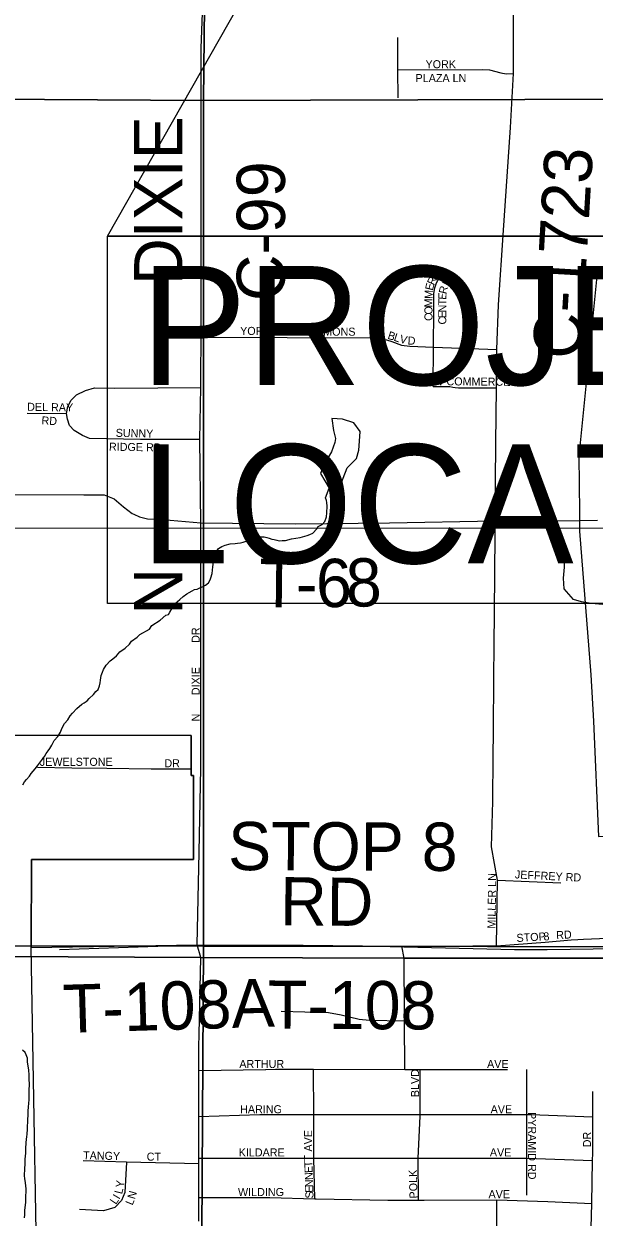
# Model space of a CAD drawing. Extents: x 8.5 to 81.5, y -1.2 to 22.4.
# Drawn here: x 51.992 to 52.663, y 15.445 to 16.85 of the extents above; entities that cross this region are included whole.
import ezdxf

# ---------------------------------------------------------------- set-up
doc = ezdxf.new("R2010")
doc.units = 0
for name, color, linetype in [('GM_X_City_Street', 7, 'Continuous'), ('GM_X_City_Street_Text', 7, 'Continuous'), ('GM_X_Corporation', 7, 'Continuous'), ('GM_X_County_Road', 7, 'Continuous'), ('GM_X_County_Road_Text', 7, 'Continuous'), ('GM_X_Interchange_Ramps', 7, 'Continuous'), ('GM_X_Minor_Lake', 7, 'Continuous'), ('GM_X_Minor_River', 7, 'Continuous'), ('GM_X_Section', 7, 'Continuous'), ('GM_X_Township', 7, 'Continuous'), ('GM_X_Township_Road', 7, 'Continuous'), ('GM_X_Township_Road_Text', 7, 'Continuous'), ('GM_X_Township_Subdivision', 7, 'Continuous'), ('GM_X_Township_Subdivision_Text', 7, 'Continuous'), ('SH_Text', 7, 'Continuous')]:
    doc.layers.add(name, color=color, linetype=linetype)

msp = doc.modelspace()

# ---------------------------------------------------------------- linework, layer by layer
at = {"layer": 'GM_X_City_Street'}
for points in [[(52.5465, 16.2011), (52.5469, 16.2508)], [(52.5454, 16.0819), (52.5457, 16.117), (52.5465, 16.2011)], [(52.1991, 15.9147), (52.2003, 15.9732), (52.2003, 16.0131), (52.2003, 16.1532)], [(52.5483, 15.7647), (52.5495, 15.8419), (52.5425, 15.881), (52.5441, 15.9345), (52.5444, 15.9879), (52.5447, 16.0167), (52.5454, 16.0819)], [(52.008, 15.9748), (52.0484, 15.9743), (52.0897, 15.9738), (52.1417, 15.9728), (52.1886, 15.9728)], [(52.1982, 15.8749), (52.1991, 15.9147)], [(52.1983, 15.66), (52.2003, 15.7506), (52.196, 15.7656), (52.1982, 15.8749)], [(52.5495, 15.8419), (52.6242, 15.8389)], [(52.5204, 15.7644), (52.5483, 15.7647), (52.6057, 15.7689), (52.6364, 15.7716), (52.6441, 15.772)], [(52.6441, 15.772), (52.651, 15.7724), (52.679, 15.7735)]]:
    msp.add_lwpolyline(points, dxfattribs=at)
at = {"layer": 'GM_X_Corporation'}
for points in [[(52.6937, 16.256), (51.6568, 16.2563), (51.671, 16.2128), (51.6596, 16.2043), (51.6444, 16.1826), (51.6447, 16.1693), (51.6783, 16.1687), (51.6973, 16.1563), (51.7134, 16.1365), (51.7024, 16.0787), (51.7477, 16.0787), (51.7477, 16.0125), (52.1887, 16.0124), (52.1887, 15.965), (52.1915, 15.965), (52.1915, 15.8662), (52.0008, 15.8662), (52.0006, 15.7624), (52.196, 15.7656), (52.3208, 15.7651), (52.3907, 15.7645), (52.5695, 15.7602), (52.6081, 15.7601), (52.771, 15.7625)], [(52.0096, 15.25), (52.0006, 15.7624), (52.0008, 15.8662), (52.1915, 15.8662), (52.1915, 15.965), (52.1887, 15.965), (52.1887, 16.0124), (51.7477, 16.0125), (51.6967, 16.0125), (51.6913, 15.9108), (51.6902, 15.7628), (51.6397, 15.762), (51.5788, 15.7609), (51.5389, 15.7615), (51.5388, 15.4213)]]:
    msp.add_lwpolyline(points, dxfattribs=at)
at = {"layer": 'GM_X_County_Road'}
for points in [[(52.2003, 16.1532), (52.2003, 16.2526), (52.2003, 16.2626), (52.199, 16.3609), (52.2003, 16.4222), (52.2004, 16.4349), (52.2008, 16.4813), (52.2007, 16.8218), (52.204, 16.9161), (52.204, 16.9504), (52.204, 17.0069), (52.2074, 17.1214), (52.2073, 17.217), (52.2073, 17.3093), (52.2079, 17.4425), (52.2107, 17.5455), (52.2107, 17.712), (52.2092, 17.8004)], [(52.5469, 16.2508), (52.547, 16.2649), (52.5478, 16.3566), (52.5484, 16.4219), (52.5487, 16.4669), (52.5508, 16.5193), (52.5568, 16.6074), (52.5596, 16.6533), (52.5649, 16.7285), (52.5685, 16.7919), (52.5684, 16.8692), (52.572, 16.9648), (52.5716, 17.035), (52.5715, 17.0497), (52.572, 17.1033), (52.572, 17.1627), (52.5744, 17.2103), (52.5768, 17.2364), (52.5815, 17.2555), (52.5934, 17.2745), (52.6101, 17.2935)], [(52.198, 15.4403), (52.198, 15.468), (52.198, 15.5079), (52.198, 15.5143), (52.198, 15.5342), (52.198, 15.5444), (52.198, 15.5636), (52.198, 15.6175), (52.198, 15.6459), (52.1983, 15.66)]]:
    msp.add_lwpolyline(points, dxfattribs=at)
at = {"layer": 'GM_X_Interchange_Ramps'}
for points in [[(52.6792, 16.557), (52.6671, 16.557), (52.6508, 16.3963), (52.6455, 16.3414), (52.6462, 16.2753), (52.6462, 16.2654)], [(52.6462, 16.2654), (52.6462, 16.2529), (52.6595, 16.0836), (52.6625, 16.029), (52.6687, 15.8932), (52.6792, 15.8938)]]:
    msp.add_lwpolyline(points, dxfattribs=at)
at = {"layer": 'GM_X_Minor_Lake'}
for points in [[(52.3513, 16.3037), (52.363, 16.3031), (52.3678, 16.3155), (52.3726, 16.3276), (52.3835, 16.3384), (52.3863, 16.3482), (52.3869, 16.3589), (52.3879, 16.3702), (52.3805, 16.3803), (52.3669, 16.3847), (52.3544, 16.3857), (52.3564, 16.3716), (52.3589, 16.3621)], [(52.3589, 16.3621), (52.358, 16.3575), (52.354, 16.3462), (52.3462, 16.3335), (52.341, 16.321), (52.3513, 16.3037)]]:
    msp.add_lwpolyline(points, dxfattribs=at)
at = {"layer": 'GM_X_Minor_River'}
for points in [[(52.0809, 16.0707), (52.0817, 16.0741), (52.0822, 16.0775), (52.083, 16.0828), (52.0843, 16.087), (52.0858, 16.09), (52.0886, 16.0949), (52.0936, 16.1001), (52.0967, 16.1027), (52.101, 16.106), (52.1049, 16.1109), (52.111, 16.1149), (52.1161, 16.1198), (52.1184, 16.1232), (52.1253, 16.128), (52.1284, 16.1313), (52.1396, 16.1375), (52.1427, 16.1417), (52.1523, 16.1479), (52.1589, 16.1539), (52.1623, 16.1546), (52.1639, 16.1576), (52.1666, 16.1621), (52.1698, 16.1674), (52.1729, 16.17), (52.1756, 16.1726), (52.1794, 16.1759), (52.1837, 16.1789), (52.1864, 16.1807), (52.1902, 16.1825), (52.1929, 16.184), (52.1959, 16.1847), (52.1998, 16.1865), (52.2028, 16.1876), (52.2059, 16.1894), (52.2094, 16.192), (52.2113, 16.1954), (52.2121, 16.198), (52.2134, 16.203), (52.2138, 16.2068), (52.2143, 16.2109), (52.2147, 16.2136), (52.2148, 16.2166), (52.2152, 16.2197), (52.2157, 16.2223), (52.2165, 16.2257), (52.2181, 16.2287), (52.2212, 16.2325), (52.225, 16.235), (52.2289, 16.2365), (52.2346, 16.2379), (52.2407, 16.2385), (52.2433, 16.2389), (52.2471, 16.2392), (52.2502, 16.2399), (52.2536, 16.2413), (52.2594, 16.2435), (52.2655, 16.246), (52.2685, 16.2463), (52.272, 16.2463), (52.275, 16.2462), (52.278, 16.2454), (52.2806, 16.2446), (52.284, 16.2433), (52.2867, 16.2429), (52.2897, 16.2421), (52.2923, 16.2417), (52.2961, 16.242), (52.2999, 16.2419), (52.3072, 16.244), (52.3171, 16.2453), (52.3255, 16.2478), (52.3285, 16.2489), (52.332, 16.2504), (52.337, 16.2556), (52.3386, 16.2582), (52.3432, 16.2608), (52.3463, 16.2641), (52.3483, 16.2698), (52.3488, 16.2743), (52.349, 16.2823), (52.3487, 16.2865), (52.3483, 16.2892), (52.3471, 16.2923), (52.3513, 16.3037)], [(52.6737, 16.1667), (52.6597, 16.1677), (52.6487, 16.1695), (52.6389, 16.1724), (52.6281, 16.1851), (52.6272, 16.1977), (52.6283, 16.2106), (52.6289, 16.2223), (52.623, 16.235), (52.6214, 16.248)], [(51.9908, 15.9543), (51.9924, 15.9577), (51.9948, 15.9603), (51.9983, 15.9644), (52.0006, 15.9674), (52.0053, 15.973), (52.008, 15.9767), (52.0138, 15.9842), (52.0162, 15.9876), (52.0182, 15.991), (52.0205, 15.994), (52.0225, 15.997), (52.0248, 16.0007), (52.0276, 16.0064), (52.0319, 16.0112), (52.035, 16.0161), (52.0366, 16.0206), (52.0398, 16.0263), (52.0436, 16.0308), (52.0464, 16.0353), (52.0491, 16.0386), (52.0542, 16.0439), (52.0603, 16.0491), (52.063, 16.0509), (52.0665, 16.0531), (52.0688, 16.0557), (52.0739, 16.0606), (52.0766, 16.0639), (52.0793, 16.0665), (52.0809, 16.0707)], [(51.9925, 15.4443), (51.9929, 15.4477), (51.993, 15.453), (51.994, 15.4621), (51.9941, 15.4697), (51.9946, 15.4751), (51.9947, 15.4785), (51.9937, 15.4853), (51.9931, 15.4903), (51.9927, 15.4937), (51.9929, 15.5021), (51.9934, 15.5074), (51.9935, 15.5131), (51.9941, 15.5203), (51.9942, 15.526), (51.9947, 15.5325), (51.9951, 15.5367), (51.9952, 15.5397), (51.9957, 15.5427), (51.9961, 15.5484), (51.9964, 15.5602), (51.9969, 15.5648), (51.997, 15.5701), (51.9974, 15.5746), (51.9975, 15.5792), (51.998, 15.583), (51.9982, 15.594), (51.9984, 15.6016), (51.9981, 15.6073), (51.9982, 15.61), (51.9979, 15.6127), (51.9976, 15.618), (51.9973, 15.621), (51.9966, 15.6252), (51.9963, 15.6279), (51.996, 15.6321), (51.9945, 15.6363), (51.9935, 15.639), (51.9901, 15.6417)]]:
    msp.add_lwpolyline(points, dxfattribs=at)
at = {"layer": 'GM_X_Section'}
for points in [[(51.2117, 17.8427), (52.2149, 17.8371), (52.2034, 16.7602), (51.2044, 16.7664)], [(52.2149, 17.8371), (53.2272, 17.8352), (53.2124, 16.7633), (52.2034, 16.7602)], [(51.2044, 16.7664), (52.2034, 16.7602), (52.2033, 15.7642), (51.1955, 15.7645)], [(52.2034, 16.7602), (53.2124, 16.7633), (53.2065, 15.7628), (52.2033, 15.7642)], [(51.1955, 15.7645), (52.2033, 15.7642), (52.1975, 14.7482), (51.1961, 14.7442)], [(52.2033, 15.7642), (53.2065, 15.7628), (53.1998, 14.754), (52.1975, 14.7482)]]:
    msp.add_lwpolyline(points, close=True, dxfattribs=at)
at = {"layer": 'GM_X_Township'}
for points in [[(51.1938, 15.7549), (51.5756, 15.7537), (51.6527, 15.7534), (52.2003, 15.7506), (52.4397, 15.7501), (52.6795, 15.7498)], [(52.6795, 15.7498), (52.4397, 15.7501), (52.2003, 15.7506), (51.6527, 15.7534), (51.5756, 15.7537), (51.1938, 15.7549)]]:
    msp.add_lwpolyline(points, dxfattribs=at)
at = {"layer": 'GM_X_Township_Road'}
for points in [[(51.7005, 16.4905), (51.7271, 16.4919), (51.7446, 16.4912), (51.7616, 16.4898), (51.7748, 16.4823), (51.7808, 16.4766), (51.7883, 16.4599), (51.7883, 16.4386), (51.789, 16.3814), (51.787, 16.3296), (51.7896, 16.3206), (51.7933, 16.3133), (51.7988, 16.307), (51.8047, 16.3023), (51.8134, 16.2983), (51.8287, 16.2959), (51.8909, 16.2965), (52.0626, 16.2957), (52.0863, 16.2957), (52.0982, 16.2909), (52.109, 16.2814), (52.1193, 16.2736), (52.1212, 16.2728)], [(52.1212, 16.2728), (52.1281, 16.2698), (52.1376, 16.2676), (52.1552, 16.2668), (52.2003, 16.2626)], [(52.2003, 16.2626), (52.3119, 16.2617), (52.4226, 16.2628), (52.547, 16.2649), (52.555, 16.265)], [(52.555, 16.265), (52.6462, 16.2654), (52.6674, 16.2657)], [(52.0337, 15.76), (52.196, 15.7656)], [(52.196, 15.7656), (52.3208, 15.7651), (52.3907, 15.7645), (52.4368, 15.7642), (52.5006, 15.7642), (52.5204, 15.7644)]]:
    msp.add_lwpolyline(points, dxfattribs=at)
at = {"layer": 'GM_X_Township_Subdivision'}
for points in [[(52.4324, 16.7964), (52.4324, 16.8307), (52.4323, 16.8344)], [(52.4324, 16.7964), (52.5322, 16.7967), (52.5322, 16.7967), (52.5403, 16.7963), (52.5534, 16.7928), (52.5596, 16.7917), (52.5685, 16.7919)], [(52.4325, 16.7632), (52.4324, 16.7964)], [(52.4737, 16.4232), (52.4742, 16.4696), (52.4746, 16.5128), (52.4748, 16.533), (52.4759, 16.5396), (52.4779, 16.5455), (52.4812, 16.5515)], [(52.2008, 16.4813), (52.4031, 16.4806), (52.4096, 16.4802), (52.4187, 16.4782), (52.4252, 16.4761), (52.4367, 16.4721), (52.4463, 16.4706), (52.4742, 16.4696), (52.5487, 16.4669)], [(52.199, 16.3609), (52.1292, 16.361), (52.0693, 16.362), (52.061, 16.3654), (52.0512, 16.3716), (52.0455, 16.3774), (52.0431, 16.3849), (52.0419, 16.3916), (52.0438, 16.3998), (52.0476, 16.4073), (52.054, 16.4133), (52.0646, 16.4186), (52.0752, 16.4219), (52.0989, 16.4213), (52.2003, 16.4222)], [(52.4737, 16.4232), (52.4934, 16.4232), (52.4971, 16.4226), (52.4999, 16.4222), (52.5038, 16.4219), (52.5484, 16.4219)], [(51.9957, 16.392), (52.0419, 16.3916)], [(52.4405, 15.619), (52.4401, 15.6759), (52.44, 15.683), (52.4397, 15.7501), (52.4368, 15.7642)], [(52.4401, 15.6759), (52.3987, 15.6764), (52.3867, 15.6777), (52.3654, 15.683), (52.3507, 15.6857), (52.2948, 15.6871)], [(52.198, 15.6175), (52.2763, 15.6189), (52.2766, 15.6189)], [(52.2766, 15.6189), (52.2881, 15.6191), (52.3329, 15.6191), (52.4405, 15.619), (52.4587, 15.619), (52.4729, 15.619), (52.4729, 15.619)], [(52.3344, 15.4666), (52.3334, 15.5145), (52.3334, 15.5658), (52.3329, 15.6191)], [(52.4585, 15.5639), (52.4586, 15.5657), (52.4587, 15.5671), (52.4587, 15.619)], [(52.4729, 15.619), (52.522, 15.619), (52.522, 15.619)], [(52.522, 15.619), (52.5613, 15.619)], [(52.584, 15.471), (52.584, 15.5144), (52.584, 15.5657), (52.584, 15.619)], [(52.6599, 15.2337), (52.6584, 15.2939), (52.6584, 15.2969), (52.6596, 15.3441), (52.66, 15.3598), (52.66, 15.4059), (52.66, 15.4325), (52.6606, 15.461), (52.6615, 15.5118), (52.6617, 15.5202), (52.6617, 15.5631), (52.6617, 15.593)], [(52.198, 15.5636), (52.2698, 15.5658), (52.3334, 15.5658), (52.4586, 15.5657), (52.584, 15.5657), (52.5889, 15.5657), (52.6617, 15.5631)], [(52.4564, 15.4648), (52.456, 15.5145), (52.4585, 15.5637), (52.4585, 15.5639)], [(52.1126, 15.5099), (52.1108, 15.4738), (52.1068, 15.4645), (52.0989, 15.4565), (52.0855, 15.4525), (52.0575, 15.4538)], [(52.198, 15.5079), (52.1126, 15.5099), (52.0615, 15.5112)], [(52.198, 15.5143), (52.2682, 15.5145), (52.3334, 15.5145), (52.456, 15.5145), (52.584, 15.5144), (52.6615, 15.5118)], [(52.198, 15.468), (52.2814, 15.4682), (52.3344, 15.4666), (52.336, 15.4665), (52.4203, 15.4649), (52.4564, 15.4648), (52.4633, 15.4648), (52.5487, 15.4655), (52.6088, 15.4632), (52.6606, 15.461)], [(52.5488, 15.1149), (52.5488, 15.1159), (52.5487, 15.1178), (52.5487, 15.1744), (52.5487, 15.2324), (52.5487, 15.293), (52.5487, 15.3466), (52.5487, 15.4086), (52.5487, 15.4655)]]:
    msp.add_lwpolyline(points, dxfattribs=at)
at = {"layer": 'SH_Text'}
for points in [[(52.7512, 17.7635), (52.6752, 16.6003), (52.0904, 16.6003)], [(52.0904, 16.6003), (53.1932, 16.6003), (53.1932, 16.1676), (52.0904, 16.1676)]]:
    msp.add_lwpolyline(points, close=True, dxfattribs=at)

# ---------------------------------------------------------------- texts
at = {"layer": 'GM_X_City_Street_Text'}
for s, rotation, p in [('DR', 90, (52.1989, 16.1213)), ('DIXIE', 90, (52.1989, 16.0597)), ('N', 90, (52.1989, 16.0288)), ('JEWELSTONE', 0, (52.0106, 15.9765)), ('DR', 0, (52.1573, 15.9748)), ('JEFFREY RD', 357.1365, (52.5699, 15.844)), ('MILLER LN', 89.2284, (52.5472, 15.7847)), ('STOP', 3.3646, (52.5722, 15.769)), ('8', 5.9436, (52.6042, 15.7706)), ('RD', 3.0224, (52.6189, 15.7723))]:
    msp.add_text(s, height=0.00947, rotation=rotation, dxfattribs=at).set_placement(p)
at = {"layer": 'GM_X_County_Road_Text'}
for s, height, rotation, p in [('DIXIE', 0.05682, 90, (52.1785, 16.543)), ('C-1723', 0.05682, 86.6499, (52.6476, 16.4546)), ('C-99', 0.05682, 90, (52.2993, 16.5238)), ('N', 0.0568, 90, (52.1785, 16.1547))]:
    msp.add_text(s, height=height, rotation=rotation, dxfattribs=at).set_placement(p)
at = {"layer": 'GM_X_Township_Road_Text'}
for s, height, rotation, p in [('T', 0.0568, 359.34, (52.2688, 16.1636)), ('6', 0.0568, 0.8585, (52.3362, 16.1632)), ('8', 0.0568, 1.0072, (52.3714, 16.1638)), ('-', 0.0568, 0.3925, (52.3124, 16.1631)), ('STOP 8', 0.05682, 359.7863, (52.2323, 15.8537)), ('RD', 0.05682, 359.5192, (52.2934, 15.7887)), ('T-108A', 0.05682, 1.7356, (52.0386, 15.6618)), ('T-108', 0.05682, 359.7223, (52.2791, 15.6669))]:
    msp.add_text(s, height=height, rotation=rotation, dxfattribs=at).set_placement(p)
at = {"layer": 'GM_X_Township_Subdivision_Text'}
for s, rotation, p in [('YORK', 0, (52.4648, 16.7981)), ('PLAZA LN', 0, (52.4531, 16.7818)), ('C', 59.8816, (52.4778, 16.5484)), ('E', 59.4486, (52.4816, 16.5548)), ('R', 60.9902, (52.496, 16.5478)), ('E', 76.0632, (52.4733, 16.5357)), ('R', 65.347, (52.4748, 16.5418)), ('D', 61.5483, (52.492, 16.5405)), ('M', 88.0326, (52.4731, 16.5263)), ('E', 88.6887, (52.4893, 16.5254)), ('R', 76.7178, (52.4894, 16.5316)), ('O', 89.8578, (52.473, 16.508)), ('M', 89.8543, (52.473, 16.5163)), ('T', 89.7814, (52.4893, 16.5188)), ('N', 90, (52.4893, 16.5105)), ('C', 89.8543, (52.473, 16.5005)), ('C', 90, (52.4893, 16.4963)), ('E', 90, (52.4893, 16.5038)), ('YORK', 0, (52.2465, 16.484)), ('COMMONS', 0, (52.3148, 16.4831)), ('B', 341.9722, (52.4195, 16.4797)), ('L', 341.9452, (52.4267, 16.4774)), ('V', 346.149, (52.4337, 16.4751)), ('D', 356.6234, (52.4436, 16.4728)), ('W COMMERCE LN', 359.5222, (52.474, 16.4248)), ('DEL RAY', 359.0457, (51.9956, 16.3947)), ('RD', 356.989, (52.0124, 16.3787)), ('SUNNY', 358.8035, (52.0999, 16.364)), ('RIDGE RD', 359.1201, (52.092, 16.3477)), ('ARTHUR', 0, (52.2456, 15.6206)), ('AVE', 0, (52.5373, 15.6206)), ('BLVD', 90, (52.4572, 15.5863)), ('HARING', 0, (52.2465, 15.5673)), ('AVE', 0, (52.5415, 15.5673)), ('PYRAMID RD', 270, (52.5856, 15.5688)), ('AVE', 90, (52.3313, 15.5222)), ('DR', 90, (52.6597, 15.5272)), ('TANGY', 358.8315, (52.0615, 15.5131)), ('CT', 0, (52.1365, 15.5115)), ('KILDARE', 0, (52.2448, 15.5165)), ('T', 91.3386, (52.3315, 15.5104)), ('AVE', 0, (52.5406, 15.5165)), ('T', 91.9947, (52.3317, 15.5038)), ('E', 92.0022, (52.332, 15.4971)), ('Y', 83.8906, (52.1094, 15.4794)), ('N', 91.9988, (52.3323, 15.4888)), ('N', 91.9988, (52.3325, 15.4804)), ('POLK', 91.5903, (52.4555, 15.4671)), ('L', 75.5838, (52.1074, 15.4715)), ('N', 73.7476, (52.1226, 15.4655)), ('WILDING', 0, (52.244, 15.4698)), ('E', 91.9674, (52.3328, 15.4738)), ('S', 91.9947, (52.333, 15.4671)), ('AVE', 0, (52.539, 15.4673)), ('L', 56.1205, (52.1002, 15.4592)), ('I', 59.4822, (52.1042, 15.4652)), ('L', 67.6912, (52.1197, 15.4583))]:
    msp.add_text(s, height=0.00947, rotation=rotation, dxfattribs=at).set_placement(p)
at = {"layer": 'SH_Text'}
for s, p in [('PROJECT', (52.1294, 16.4251)), ('LOCATION', (52.1294, 16.2151))]:
    msp.add_text(s, height=0.14, dxfattribs=at).set_placement(p)

doc.saveas('drawing.dxf')
